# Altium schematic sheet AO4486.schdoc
size 127 x 101 mm
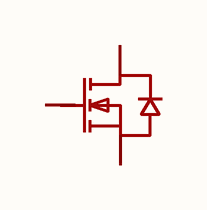
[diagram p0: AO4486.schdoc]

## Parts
Q?  ao4486  [SOP-8_L5.0-W3.8-P1.27-LS6.0-BL]  (value not drawn)

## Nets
NetQ?_1: Q?.1(S) Q?.2(S) Q?.3(S)
NetQ?_5: Q?.5(D) Q?.6(D) Q?.7(D) Q?.8(D)

Not connected (* = marked no-connect by the designer): Q? 4(G)

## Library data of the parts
Q? = ao4486: 数量:1个N沟道;漏源电压(Vdss):100V;连续漏极电流(Id):4.2A;导通电阻(RDS(on)):69mΩ@10V;耗散功率(Pd):3.1W;阈值电压(Vgs(th)):2.2V@250uA;; Manufacturer: UMW(友台半导体); AddInBom: yes; ModelId: 823e4ad1ee284f09bfed9f55dae295e0; ModelTransform: 196.85,236.22,0,0,0,0,0,0,0; Number: 1个N沟道; Drain to Source Voltage: 100V; Current - Continuous Drain(Id): 4.2A; Pd - Power Dissipation: 3.1W; Gate Charge(Qg): 16.3nC@10V; Input Capacitance(Ciss): 778pF; Reverse Transfer Capacitance (Crss@Vds): 24pF; Type: N沟道; Output Capacitance(Coss): 55pF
